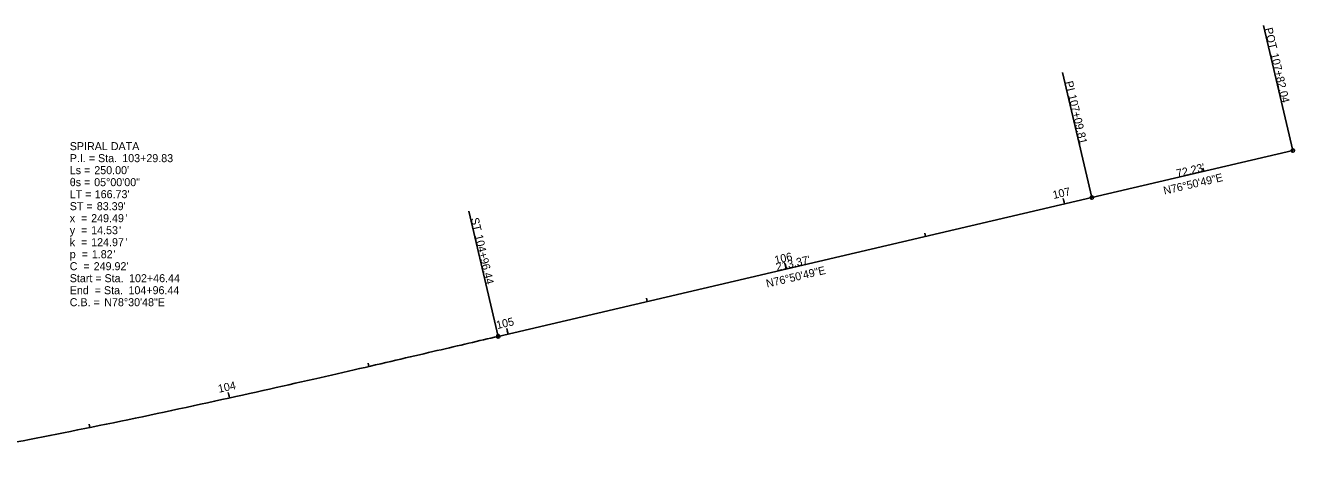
# Model space of a CAD drawing. Extents: x 1999336 to 2003366, y 252766 to 253936.
# Drawn here: x 2002921.4 to 2003365.5, y 252780.6 to 252939.2 of the extents above; entities that cross this region are included whole.
import ezdxf

# ---------------------------------------------------------------- set-up
doc = ezdxf.new("R2010")
doc.units = 0
for name, color, linetype in [('GE_X_CL_20', 7, 'Continuous'), ('GK_Visualization', 7, 'Continuous'), ('RW_X_Esmt_SH', 7, 'Continuous'), ('SC_Scratch3', 7, 'Continuous'), ('SV_X_Control_Cells_Found', 7, 'Continuous'), ('SV_X_Text_Elevation', 7, 'Continuous'), ('SV_X_Text_Name', 7, 'Continuous')]:
    doc.layers.add(name, color=color, linetype=linetype)

msp = doc.modelspace()

# ---------------------------------------------------------------- linework, layer by layer
at = {"layer": 'GE_X_CL_20'}
for p, q in [((2003364.94, 252895.34), (2003354.7, 252939.16)), ((2003294.6, 252878.9), (2003284.36, 252922.72)), ((2003285.05, 252876.67), (2003284.78, 252877.84)), ((2003086.83, 252830.35), (2003076.59, 252874.17)), ((2003187.67, 252853.91), (2003187.4, 252855.08)), ((2003090.3, 252831.16), (2003089.84, 252833.11)), ((2002992.83, 252808.81), (2002992.57, 252809.98))]:
    msp.add_line(p, q, dxfattribs=at)
for centre in [(2003364.94, 252895.34), (2003294.6, 252878.9), (2003086.83, 252830.35)]:
    msp.add_circle(centre, 0.6, dxfattribs=at)
at = {"layer": 'GK_Visualization'}
for p, q in [((2003294.6, 252878.9), (2003364.94, 252895.34)), ((2003086.83, 252830.35), (2003294.6, 252878.9))]:
    msp.add_line(p, q, dxfattribs=at)
msp.add_open_spline([(2002841.92, 252780.58), (2002848.79, 252781.56), (2002862.53, 252783.63), (2002889.94, 252788.14), (2002924.09, 252794.39), (2002964.93, 252802.69), (2003005.63, 252811.58), (2003039.48, 252819.32), (2003066.54, 252825.61), (2003080.07, 252828.77), (2003086.83, 252830.35)], degree=3, dxfattribs=at)
msp.add_open_spline([(2002841.92, 252780.58), (2002848.79, 252781.56), (2002862.53, 252783.63), (2002889.94, 252788.14), (2002924.09, 252794.39), (2002964.93, 252802.69), (2003005.63, 252811.58), (2003039.48, 252819.32), (2003066.54, 252825.61), (2003080.07, 252828.77), (2003086.83, 252830.35)], degree=3, dxfattribs=at)
at = {"layer": 'SC_Scratch3'}
for p, q in [((2003364.94, 252895.34), (2003354.7, 252939.16)), ((2003294.6, 252878.9), (2003284.36, 252922.72)), ((2003333.74, 252888.05), (2003333.46, 252889.21)), ((2003285.05, 252876.67), (2003284.59, 252878.62)), ((2003086.83, 252830.35), (2003076.59, 252874.17)), ((2003236.36, 252865.29), (2003236.09, 252866.46)), ((2003187.67, 252853.91), (2003187.22, 252855.86)), ((2003138.98, 252842.54), (2003138.71, 252843.7)), ((2003090.3, 252831.16), (2003089.84, 252833.11)), ((2003041.6, 252819.83), (2003041.33, 252820.99)), ((2002992.83, 252808.81), (2002992.4, 252810.76)), ((2002943.91, 252798.45), (2002943.67, 252799.63))]:
    msp.add_line(p, q, dxfattribs=at)
for centre in [(2003364.94, 252895.34), (2003294.6, 252878.9), (2003086.83, 252830.35)]:
    msp.add_circle(centre, 0.6, dxfattribs=at)
at = {"layer": 'SV_X_Text_Name'}
for p, q in [((2003364.94, 252895.34), (2003354.7, 252939.16)), ((2003294.6, 252878.9), (2003284.36, 252922.72)), ((2003086.83, 252830.35), (2003076.59, 252874.17)), ((2003090.3, 252831.16), (2003090.02, 252832.33))]:
    msp.add_line(p, q, dxfattribs=at)
for centre in [(2003364.94, 252895.34), (2003294.6, 252878.9), (2003086.83, 252830.35)]:
    msp.add_circle(centre, 0.6, dxfattribs=at)

# ---------------------------------------------------------------- texts
at = {"layer": 'GE_X_CL_20'}
for s, rotation, p in [('POT', 283.1531, (2003355.01, 252938.04)), ('107+82.04', 283.1531, (2003357.08, 252929.14)), ('PI', 283.1531, (2003285.19, 252919.36)), ('107+09.81', 283.1531, (2003286.28, 252914.7)), ("72.23'", 13.1531, (2003324.5, 252885.94)), ('N76°50\'49"E', 13.1531, (2003319.97, 252879.9)), ('ST', 283.1531, (2003077.24, 252871.56)), ('104+96.44', 283.1531, (2003078.63, 252865.64)), ("213.37'", 13.1531, (2003184.39, 252853.19)), ('N76°50\'49"E', 13.1531, (2003180.92, 252847.41)), ('105', 13.1531, (2003086.51, 252832.89))]:
    msp.add_text(s, height=2.8, rotation=rotation, dxfattribs=at).set_placement(p)
at = {"layer": 'RW_X_Esmt_SH'}
for s, p in [('SPIRAL DATA', (2002936.91, 252895.5)), ('P.I. = Sta. ', (2002936.91, 252891.3)), ('103+29.83', (2002955.28, 252891.3)), ('Ls = ', (2002936.91, 252887.1)), ("250.00'", (2002945.5, 252887.1)), ('θs = ', (2002936.91, 252882.9)), ('05°00\'00"', (2002945.45, 252882.9)), ('LT = ', (2002936.91, 252878.7)), ("166.73'", (2002945.64, 252878.7)), ('ST = ', (2002936.91, 252874.5)), ("83.39'", (2002946.37, 252874.5)), ('x  = ', (2002936.91, 252870.3)), ('249.49', (2002944.41, 252870.3)), ("'", (2002956.37, 252870.3)), ('y  = ', (2002936.91, 252866.1)), ('14.53', (2002944.41, 252866.1)), ("'", (2002954.2, 252866.1)), ('k  = ', (2002936.91, 252861.9)), ('124.97', (2002944.41, 252861.9)), ("'", (2002956.37, 252861.9)), ('p  = ', (2002936.91, 252857.7)), ('1.82', (2002944.63, 252857.7)), ("'", (2002952.24, 252857.7)), ('C  = ', (2002936.91, 252853.5)), ("249.92'", (2002945.28, 252853.5)), ('Start = Sta. ', (2002936.91, 252849.3)), ('End  = Sta. ', (2002936.91, 252845.1)), ('104+96.44', (2002957.46, 252845.1)), ('102+46.44', (2002957.67, 252849.3)), ('C.B. = ', (2002936.91, 252840.9)), ('N78°30\'48"E', (2002948.98, 252840.9))]:
    msp.add_text(s, height=2.8, dxfattribs=at).set_placement(p)
at = {"layer": 'SC_Scratch3'}
for s, rotation, p in [('POT', 283.1531, (2003355.01, 252938.04)), ('107+82.04', 283.1531, (2003357.08, 252929.14)), ('PI', 283.1531, (2003285.19, 252919.36)), ('107+09.81', 283.1531, (2003286.28, 252914.7)), ("72.23'", 13.1531, (2003324.5, 252885.94)), ('N76°50\'49"E', 13.1531, (2003319.97, 252879.9)), ('107', 13.1531, (2003281.22, 252878.39)), ('ST', 283.1531, (2003077.24, 252871.56)), ('104+96.44', 283.1531, (2003078.63, 252865.64)), ('106', 13.1531, (2003183.89, 252855.65)), ("213.37'", 13.1531, (2003184.39, 252853.19)), ('N76°50\'49"E', 13.1531, (2003180.92, 252847.41)), ('105', 13.1531, (2003086.51, 252832.89)), ('104', 12.4091, (2002989.12, 252810.6))]:
    msp.add_text(s, height=2.8, rotation=rotation, dxfattribs=at).set_placement(p)
at = {"layer": 'SV_X_Control_Cells_Found'}
for s, p in [('SPIRAL DATA', (2002936.91, 252895.5)), ('P.I. = Sta. ', (2002936.91, 252891.3)), ('103+29.83', (2002955.28, 252891.3)), ('Ls = ', (2002936.91, 252887.1)), ("250.00'", (2002945.5, 252887.1)), ('θs = ', (2002936.91, 252882.9)), ('05°00\'00"', (2002945.45, 252882.9)), ('LT = ', (2002936.91, 252878.7)), ("166.73'", (2002945.64, 252878.7)), ('ST = ', (2002936.91, 252874.5)), ("83.39'", (2002946.37, 252874.5)), ('x  = ', (2002936.91, 252870.3)), ('249.49', (2002944.41, 252870.3)), ("'", (2002956.37, 252870.3)), ('y  = ', (2002936.91, 252866.1)), ('14.53', (2002944.41, 252866.1)), ("'", (2002954.2, 252866.1)), ('k  = ', (2002936.91, 252861.9)), ('124.97', (2002944.41, 252861.9)), ("'", (2002956.37, 252861.9)), ('p  = ', (2002936.91, 252857.7)), ('1.82', (2002944.63, 252857.7)), ("'", (2002952.24, 252857.7)), ('C  = ', (2002936.91, 252853.5)), ("249.92'", (2002945.28, 252853.5)), ('Start = Sta. ', (2002936.91, 252849.3)), ('End  = Sta. ', (2002936.91, 252845.1)), ('104+96.44', (2002957.46, 252845.1)), ('102+46.44', (2002957.67, 252849.3)), ('C.B. = ', (2002936.91, 252840.9)), ('N78°30\'48"E', (2002948.98, 252840.9))]:
    msp.add_text(s, height=2.8, dxfattribs=at).set_placement(p)
at = {"layer": 'SV_X_Text_Elevation'}
for s, p in [('SPIRAL DATA', (2002936.91, 252895.5)), ('P.I. = Sta. ', (2002936.91, 252891.3)), ('103+29.83', (2002955.28, 252891.3)), ('Ls = ', (2002936.91, 252887.1)), ("250.00'", (2002945.5, 252887.1)), ('θs = ', (2002936.91, 252882.9)), ('05°00\'00"', (2002945.45, 252882.9)), ('LT = ', (2002936.91, 252878.7)), ("166.73'", (2002945.64, 252878.7)), ('ST = ', (2002936.91, 252874.5)), ("83.39'", (2002946.37, 252874.5)), ('x  = ', (2002936.91, 252870.3)), ('249.49', (2002944.41, 252870.3)), ("'", (2002956.37, 252870.3)), ('y  = ', (2002936.91, 252866.1)), ('14.53', (2002944.41, 252866.1)), ("'", (2002954.2, 252866.1)), ('k  = ', (2002936.91, 252861.9)), ('124.97', (2002944.41, 252861.9)), ("'", (2002956.37, 252861.9)), ('p  = ', (2002936.91, 252857.7)), ('1.82', (2002944.63, 252857.7)), ("'", (2002952.24, 252857.7)), ('C  = ', (2002936.91, 252853.5)), ("249.92'", (2002945.28, 252853.5)), ('Start = Sta. ', (2002936.91, 252849.3)), ('End  = Sta. ', (2002936.91, 252845.1)), ('104+96.44', (2002957.46, 252845.1)), ('102+46.44', (2002957.67, 252849.3)), ('C.B. = ', (2002936.91, 252840.9)), ('N78°30\'48"E', (2002948.98, 252840.9))]:
    msp.add_text(s, height=2.8, dxfattribs=at).set_placement(p)
at = {"layer": 'SV_X_Text_Name'}
for s, rotation, p in [('POT', 283.1531, (2003355.01, 252938.04)), ('107+82.04', 283.1531, (2003357.08, 252929.14)), ('PI', 283.1531, (2003285.19, 252919.36)), ('107+09.81', 283.1531, (2003286.28, 252914.7)), ("72.23'", 13.1531, (2003324.5, 252885.94)), ('N76°50\'49"E', 13.1531, (2003319.97, 252879.9)), ('ST', 283.1531, (2003077.24, 252871.56)), ('104+96.44', 283.1531, (2003078.63, 252865.64)), ("213.37'", 13.1531, (2003184.39, 252853.19)), ('N76°50\'49"E', 13.1531, (2003180.92, 252847.41))]:
    msp.add_text(s, height=2.8, rotation=rotation, dxfattribs=at).set_placement(p)

doc.saveas('drawing.dxf')
